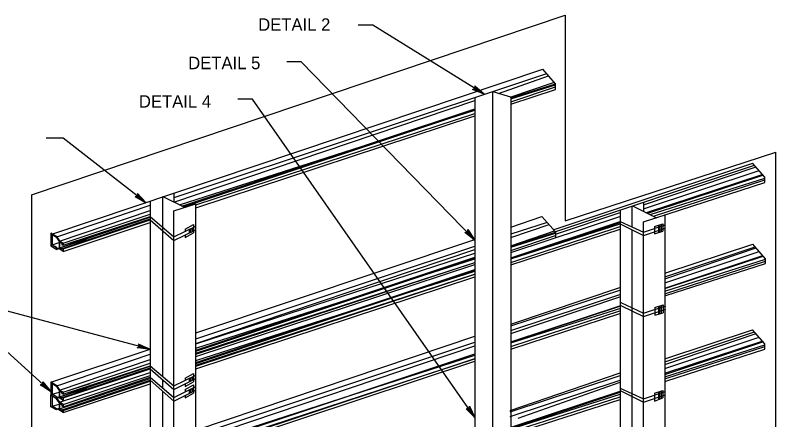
# Model space of a CAD drawing. Extents: x 650495 to 651400, y 297864 to 299646.
# Drawn here: x 650810.5 to 650993.8, y 298185.7 to 298283.1 of the extents above; entities that cross this region are included whole.
import ezdxf

# ---------------------------------------------------------------- set-up
doc = ezdxf.new("R2010")
doc.units = 0
doc.layers.add('2', color=7, linetype='Continuous')
doc.layers.add('3', color=7, linetype='Continuous')

# ---------------------------------------------------------------- blocks, each defined once
blk = doc.blocks.new('RARROW')
at = {"layer": '3'}
blk.add_lwpolyline([(-2.2695, 0.285), (-2.184875, 0.12075), (0, 0), (-2.2695, 0.285), (-2.38575, 0.384625), (0, 0), (-2.183125, -0.108), (-2.262875, -0.2705), (0, 0), (-2.38575, -0.379125), (-2.262875, -0.2705)], dxfattribs=at)

msp = doc.modelspace()

# ---------------------------------------------------------------- linework, layer by layer
at = {"layer": '2'}
for p, q in [((650814.44, 298239.88), (650943.06, 298283.13)), ((650943.06, 298283.13), (650943.06, 298233.63)), ((650896.69, 298280.75), (650893.19, 298280.75)), ((650923.56, 298264.13), (650896.69, 298280.75)), ((650879.44, 298271.88), (650875.94, 298271.88)), ((650921.31, 298229), (650879.44, 298271.88)), ((650819.31, 298230.38), (650937.69, 298270.13)), ((650940.69, 298266.63), (650937.69, 298270.13)), ((650938.56, 298269), (650848.69, 298239.13)), ((650926.97, 298264.31), (650939.06, 298268.5)), ((650929.81, 298263.42), (650940.44, 298267)), ((650929.94, 298263.25), (650940.69, 298266.63)), ((650929.94, 298263), (650940.69, 298266.38)), ((650940.69, 298265.25), (650940.69, 298266.75)), ((650925.56, 298264.68), (650925.56, 298177.88)), ((650929.94, 298263.38), (650925.67, 298264.72)), ((650929.94, 298262.25), (650940.69, 298265.88)), ((650929.94, 298261.75), (650940.69, 298265.25)), ((650848.69, 298238.13), (650921.31, 298262.63)), ((650867.69, 298262.88), (650864.19, 298262.88)), ((650921.31, 298186.25), (650867.69, 298262.88)), ((650921.31, 298263.27), (650921.31, 298176.13)), ((650929.94, 298263.38), (650929.94, 298176.38)), ((650850.69, 298237.13), (650921.31, 298260.63)), ((650850.06, 298237.5), (650921.31, 298260.25)), ((650851.06, 298237), (650921.31, 298260.38)), ((650854.06, 298237.5), (650921.31, 298259.5)), ((650854.06, 298236.75), (650921.31, 298258.88)), ((650822.06, 298253.5), (650817.94, 298253.5)), ((650842.06, 298238), (650822.06, 298253.5)), ((650943.06, 298233.63), (650993.81, 298250.13)), ((650993.81, 298139.38), (650993.81, 298250.13)), ((650940.19, 298231.5), (650988.31, 298247.5)), ((650940.56, 298231), (650988.69, 298247)), ((650961.94, 298237.5), (650989.06, 298246.63)), ((650991.19, 298244.13), (650988.19, 298247.5)), ((650961.94, 298236.5), (650989.81, 298245.75)), ((650962.69, 298235.63), (650990.56, 298244.75)), ((650962.94, 298235.5), (650990.69, 298244.63)), ((650991.19, 298242.88), (650991.19, 298244.13)), ((650961.94, 298233.38), (650991.19, 298242.88)), ((650963.56, 298235.13), (650991.19, 298243.88)), ((650964.31, 298234.75), (650991.19, 298243.5)), ((650814.44, 298240), (650814.44, 298080)), ((650846.06, 298239.5), (650851.31, 298236.88)), ((650846.06, 298196.13), (650846.06, 298239.5)), ((650848.69, 298240.25), (650848.69, 298238.13)), ((650820.56, 298229.75), (650843.06, 298237.38)), ((650843.06, 298238.38), (650843.06, 298070.13)), ((650848.69, 298236), (650854.06, 298237.75)), ((650854.06, 298067.88), (650854.06, 298237.75)), ((650959.19, 298232.13), (650959.19, 298237.25)), ((650959.31, 298237.25), (650965.06, 298234.38)), ((650961.94, 298238), (650961.94, 298236)), ((650821.19, 298228.75), (650843.06, 298236.13)), ((650822.06, 298228.25), (650843.06, 298235.25)), ((650848.69, 298065.25), (650848.69, 298236)), ((650940.69, 298230.38), (650956.31, 298235.63)), ((650956.31, 298236.25), (650956.31, 298110.5)), ((650967.19, 298108.25), (650967.19, 298235.13)), ((650821.19, 298227.13), (650843.06, 298234.5)), ((650821.81, 298227), (650843.06, 298234.13)), ((650822.06, 298227.75), (650843.06, 298234.63)), ((650822.06, 298226.88), (650843.06, 298233.88)), ((650822.06, 298226.25), (650843.06, 298233.25)), ((650843.06, 298234.63), (650848.69, 298229.75)), ((650843.06, 298233.88), (650848.69, 298228.88)), ((650843.06, 298233.25), (650843.06, 298233.25)), ((650929.94, 298226), (650956.44, 298234.75)), ((650929.94, 298232.13), (650937.44, 298234.63)), ((650929.94, 298224.75), (650956.31, 298233.5)), ((650938.69, 298233.25), (650929.94, 298230.38)), ((650929.94, 298224.5), (650956.31, 298233.25)), ((650937.44, 298234.63), (650940.69, 298231)), ((650956.31, 298233.5), (650961.94, 298230.88)), ((650961.94, 298105.63), (650961.94, 298233.38)), ((650848.69, 298229.75), (650854.06, 298232.38)), ((650848.69, 298228.88), (650854.06, 298231.5)), ((650851.44, 298231.63), (650853.44, 298232.75)), ((650851.44, 298231.63), (650851.44, 298231)), ((650852.44, 298231.63), (650852.44, 298230.75)), ((650852.69, 298231.75), (650852.69, 298230.88)), ((650853.06, 298231.88), (650853.06, 298231.13)), ((650853.31, 298232), (650853.31, 298231.25)), ((650853.44, 298232.75), (650853.44, 298230.75)), ((650929.94, 298224.5), (650956.31, 298232.88)), ((650929.94, 298229.63), (650939.19, 298232.75)), ((650929.94, 298223.63), (650956.31, 298232.25)), ((650929.94, 298223), (650956.31, 298231.63)), ((650929.94, 298227.63), (650940.44, 298231.25)), ((650956.31, 298232.88), (650961.94, 298230.13)), ((650959.19, 298108), (650959.19, 298231.5)), ((650961.94, 298230.88), (650967.19, 298232.63)), ((650961.94, 298230.13), (650967.19, 298231.88)), ((650964.56, 298232.25), (650966.56, 298232.88)), ((650964.56, 298232.25), (650964.56, 298230.5)), ((650964.56, 298230.5), (650966.56, 298231.13)), ((650965.56, 298232.63), (650965.56, 298230.75)), ((650965.81, 298232.63), (650965.81, 298230.88)), ((650966.19, 298232.75), (650966.19, 298231)), ((650966.56, 298232.88), (650966.56, 298231.13)), ((650819.06, 298230.63), (650819.06, 298230.63)), ((650820.56, 298229.75), (650819.06, 298230.63)), ((650819.06, 298230.63), (650819.06, 298227.63)), ((650819.06, 298230.63), (650820.56, 298229.75)), ((650819.44, 298230.25), (650819.44, 298227.75)), ((650820.44, 298229.63), (650819.44, 298230.25)), ((650820.44, 298229.63), (650821.06, 298228.63)), ((650820.56, 298229.75), (650821.19, 298228.75)), ((650822.06, 298228.25), (650828.56, 298230.38)), ((650822.06, 298227.75), (650828.56, 298229.88)), ((650851.44, 298229.63), (650853.44, 298230.75)), ((650851.44, 298230.25), (650851.44, 298229.63)), ((650929.94, 298227.5), (650940.69, 298230.88)), ((650929.94, 298227.25), (650940.69, 298230.63)), ((650929.94, 298226.5), (650940.69, 298230.13)), ((650940.69, 298231), (650940.69, 298229.5)), ((650819.06, 298227.63), (650820.56, 298226.75)), ((650819.44, 298227.88), (650821.06, 298228.38)), ((650820.69, 298227), (650819.44, 298227.75)), ((650820.44, 298227.25), (650819.44, 298227.75)), ((650821.06, 298228.75), (650821.06, 298227.13)), ((650821.19, 298227.13), (650827.69, 298229.25)), ((650822.06, 298228.25), (650821.19, 298228.75)), ((650821.81, 298228.13), (650821.19, 298228.5)), ((650821.81, 298228.13), (650821.19, 298228.5)), ((650821.19, 298228.5), (650821.19, 298227.13)), ((650821.81, 298228.13), (650821.81, 298227.88)), ((650821.81, 298227.75), (650821.81, 298228.13)), ((650822.06, 298227.75), (650821.81, 298227.88)), ((650822.06, 298227.75), (650821.81, 298227.75)), ((650822.06, 298228.25), (650822.06, 298227.75)), ((650822.06, 298228.25), (650822.06, 298227.75)), ((650854.06, 298206.63), (650921.31, 298229.13)), ((650854.06, 298205.25), (650921.31, 298227.5)), ((650967.31, 298221.13), (650988.31, 298228)), ((650991.31, 298224.5), (650988.31, 298228)), ((650821.06, 298226.88), (650820.56, 298226.75)), ((650820.69, 298227), (650821.06, 298227.13)), ((650822.06, 298226.25), (650821.06, 298226.88)), ((650821.81, 298226.75), (650821.19, 298227.13)), ((650821.81, 298227), (650821.81, 298226.75)), ((650822.06, 298226.88), (650821.81, 298227)), ((650821.81, 298227), (650821.81, 298226.75)), ((650822.06, 298226.88), (650821.81, 298227)), ((650822.06, 298226.88), (650822.06, 298226.25)), ((650822.06, 298226.88), (650822.06, 298226.25)), ((650854.06, 298204.13), (650921.31, 298226.75)), ((650854.06, 298204), (650921.31, 298225.88)), ((650967.31, 298220.25), (650988.81, 298227.38)), ((650967.31, 298219.75), (650989.06, 298227.13)), ((650967.31, 298218.75), (650989.81, 298226.25)), ((650854.06, 298202.5), (650921.31, 298224.88)), ((650854.06, 298202.25), (650921.31, 298224.63)), ((650854.06, 298203), (650921.31, 298224.5)), ((650967.31, 298217.5), (650990.69, 298225.25)), ((650967.31, 298217.38), (650990.81, 298225.13)), ((650967.31, 298216.75), (650991.31, 298224.38)), ((650967.31, 298216.13), (650991.31, 298223.88)), ((650991.31, 298223.38), (650991.31, 298224.5)), ((650854.06, 298201.5), (650921.31, 298223.63)), ((650854.06, 298201.75), (650921.31, 298223.63)), ((650854.06, 298201), (650921.31, 298223.13)), ((650967.31, 298215.63), (650991.31, 298223.38)), ((650854.06, 298199.5), (650921.31, 298221.88)), ((650854.06, 298199.25), (650921.31, 298221.75)), ((650854.06, 298200), (650921.31, 298221.5)), ((650854.06, 298198.63), (650921.31, 298220.75)), ((650854.06, 298198.88), (650921.19, 298220.75)), ((650854.06, 298198), (650921.31, 298220.13)), ((650929.94, 298208.75), (650956.44, 298217.63)), ((650929.94, 298208.38), (650956.44, 298217)), ((650929.94, 298207.25), (650956.44, 298216)), ((650929.94, 298206.5), (650956.44, 298215.38)), ((650929.94, 298204.5), (650956.44, 298213.25)), ((650929.94, 298204.38), (650956.44, 298213.13)), ((650956.44, 298214), (650961.94, 298211.38)), ((650956.44, 298213.25), (650961.94, 298210.63)), ((650961.94, 298211.38), (650967.31, 298213.13)), ((650964.69, 298212.75), (650966.69, 298213.38)), ((650965.56, 298213), (650965.56, 298211.25)), ((650965.81, 298213.13), (650965.81, 298211.25)), ((650966.19, 298213.25), (650966.19, 298211.38)), ((650966.69, 298213.38), (650966.69, 298211.5)), ((650842.94, 298202.75), (650805.19, 298212.75)), ((650929.94, 298204.25), (650956.44, 298212.63)), ((650929.94, 298203.38), (650956.44, 298212)), ((650929.94, 298202.75), (650956.44, 298211.38)), ((650961.94, 298210.63), (650967.31, 298212.38)), ((650964.69, 298212.75), (650964.69, 298210.88)), ((650964.69, 298210.88), (650966.69, 298211.5)), ((650967.31, 298200.5), (650988.19, 298207.38)), ((650991.19, 298204), (650988.19, 298207.38)), ((650854.06, 298183.25), (650921.31, 298205.88)), ((650967.31, 298199.75), (650988.69, 298206.88)), ((650967.31, 298199.13), (650989.06, 298206.5)), ((650967.31, 298198.13), (650989.81, 298205.63)), ((650819.06, 298192.5), (650806.56, 298203.88)), ((650854.06, 298182), (650921.31, 298204.38)), ((650967.31, 298197), (650990.56, 298204.63)), ((650967.31, 298196.75), (650990.69, 298204.5)), ((650967.31, 298196.13), (650991.19, 298203.75)), ((650991.19, 298202.75), (650991.19, 298204)), ((650819.06, 298194.75), (650843.06, 298202.75)), ((650854.06, 298180.88), (650921.31, 298203.5)), ((650967.31, 298195.63), (650991.19, 298203.38)), ((650967.31, 298195), (650991.19, 298202.75)), ((650820.56, 298193.88), (650843.06, 298201.5)), ((650821.19, 298192.88), (650843.06, 298200.25)), ((650854.06, 298179.25), (650921.31, 298201.63)), ((650854.06, 298179.63), (650921.31, 298201.25)), ((650854.06, 298178.25), (650921.31, 298200.5)), ((650854.06, 298178.5), (650921.19, 298200.38)), ((650821.19, 298191.25), (650843.06, 298198.63)), ((650821.81, 298191.13), (650843.06, 298198.25)), ((650822.06, 298192.38), (650843.06, 298199.38)), ((650822.06, 298191.88), (650843.06, 298198.75)), ((650843.06, 298198.75), (650848.69, 298193.88)), ((650854.06, 298177.63), (650921.31, 298199.88)), ((650821.19, 298190), (650843.06, 298197.13)), ((650822.06, 298191), (650843.06, 298198)), ((650822.06, 298189.38), (650843.06, 298196.38)), ((650843.06, 298198), (650848.69, 298193)), ((650843.06, 298197.38), (650843.06, 298197.38)), ((650848.69, 298193.88), (650854.06, 298196.5)), ((650851.44, 298195.75), (650853.44, 298196.88)), ((650853.44, 298196.88), (650853.44, 298194.88)), ((650929.81, 298188), (650956.31, 298197)), ((650929.81, 298187.63), (650956.31, 298196.38)), ((650820.56, 298193.88), (650819.06, 298194.75)), ((650819.06, 298194.75), (650819.06, 298191.75)), ((650819.06, 298194.75), (650820.56, 298193.88)), ((650821.19, 298188.38), (650843.06, 298195.63)), ((650821.81, 298188.13), (650843.06, 298195.25)), ((650822.06, 298188.88), (650843.06, 298196)), ((650822.06, 298188), (650843.06, 298195)), ((650822.06, 298192.38), (650828.56, 298194.5)), ((650843.06, 298196), (650848.69, 298191.13)), ((650843.06, 298195.25), (650848.69, 298190.25)), ((650843.06, 298194.63), (650843.06, 298194.63)), ((650846.06, 298193.38), (650846.06, 298195.38)), ((650848.69, 298193), (650854.06, 298195.63)), ((650851.44, 298195.75), (650851.44, 298195.25)), ((650851.44, 298193.75), (650853.44, 298194.88)), ((650852.44, 298195.75), (650852.44, 298194.88)), ((650852.69, 298195.88), (650852.69, 298195)), ((650853.06, 298196), (650853.06, 298195.25)), ((650853.31, 298196.13), (650853.31, 298195.38)), ((650929.81, 298186.5), (650956.31, 298195.25)), ((650931.69, 298186.13), (650956.31, 298194.75)), ((650819.44, 298194.38), (650819.44, 298191.88)), ((650820.44, 298193.75), (650819.44, 298194.38)), ((650820.44, 298193.75), (650821.06, 298192.75)), ((650820.56, 298193.88), (650821.19, 298192.88)), ((650821.06, 298192.75), (650821.06, 298191.25)), ((650821.19, 298191.25), (650827.69, 298193.38)), ((650822.06, 298192.38), (650821.19, 298192.88)), ((650821.81, 298192.25), (650821.19, 298192.63)), ((650821.81, 298192.25), (650821.19, 298192.63)), ((650821.19, 298192.63), (650821.19, 298191.25)), ((650822.06, 298187.5), (650843.06, 298194.38)), ((650822.06, 298191.88), (650828.56, 298194)), ((650846.06, 298067.63), (650846.06, 298192.63)), ((650848.69, 298191.13), (650854.06, 298193.75)), ((650848.69, 298190.25), (650854.06, 298192.88)), ((650851.44, 298194.38), (650851.44, 298193.75)), ((650851.44, 298193), (650853.44, 298194.13)), ((650851.44, 298193), (650851.44, 298192.5)), ((650852.44, 298193), (650852.44, 298192.13)), ((650852.69, 298193.13), (650852.69, 298192.25)), ((650853.06, 298193.25), (650853.06, 298192.5)), ((650853.31, 298193.38), (650853.31, 298192.63)), ((650853.44, 298194.13), (650853.44, 298192.13)), ((650929.81, 298183.88), (650956.31, 298192.63)), ((650956.31, 298193.38), (650961.94, 298190.75)), ((650956.31, 298192.75), (650961.94, 298190)), ((650964.56, 298192.13), (650966.56, 298192.75)), ((650966.19, 298192.63), (650966.19, 298190.88)), ((650966.56, 298192.75), (650966.56, 298191)), ((650819.06, 298188.88), (650819.06, 298191.75)), ((650819.06, 298191.75), (650820.56, 298190.88)), ((650819.44, 298191.88), (650821.06, 298192.38)), ((650820.69, 298191.13), (650819.44, 298191.88)), ((650819.44, 298191.38), (650819.44, 298189)), ((650820.44, 298190.75), (650819.44, 298191.38)), ((650821.06, 298191), (650820.56, 298190.88)), ((650820.56, 298190.88), (650821.19, 298190)), ((650820.69, 298191.13), (650821.06, 298191.25)), ((650822.06, 298190.38), (650821.06, 298191)), ((650821.81, 298190.88), (650821.19, 298191.25)), ((650821.81, 298192.25), (650821.81, 298192)), ((650821.81, 298192), (650821.81, 298192.25)), ((650822.06, 298191.88), (650821.81, 298192)), ((650821.81, 298191.13), (650821.81, 298190.88)), ((650822.06, 298191), (650821.81, 298191.13)), ((650821.81, 298191.13), (650821.81, 298190.88)), ((650822.06, 298191), (650821.81, 298191.13)), ((650822.06, 298192.38), (650822.06, 298191.88)), ((650822.06, 298192.38), (650822.06, 298191.88)), ((650822.06, 298191), (650822.06, 298190.38)), ((650822.06, 298191), (650822.06, 298190.38)), ((650851.44, 298191), (650853.44, 298192.13)), ((650851.44, 298191.63), (650851.44, 298191)), ((650929.81, 298183.63), (650956.31, 298192.38)), ((650929.81, 298183.5), (650956.31, 298191.88)), ((650929.81, 298182.75), (650956.31, 298191.25)), ((650961.94, 298190.75), (650967.19, 298192.5)), ((650961.94, 298190), (650967.19, 298191.75)), ((650964.56, 298192.13), (650964.56, 298190.25)), ((650964.56, 298190.25), (650966.56, 298191)), ((650965.56, 298192.38), (650965.56, 298190.63)), ((650965.81, 298192.5), (650965.81, 298190.75)), ((650819.44, 298189), (650821.06, 298189.5)), ((650820.44, 298188.38), (650819.44, 298189)), ((650821.06, 298189.88), (650820.44, 298190.75)), ((650821.06, 298189.88), (650821.06, 298188.5)), ((650822.06, 298189.38), (650821.19, 298190)), ((650821.81, 298189.25), (650821.19, 298189.75)), ((650821.19, 298189.75), (650821.19, 298188.38)), ((650821.81, 298189), (650821.81, 298189.25)), ((650822.06, 298188.88), (650821.81, 298189)), ((650822.06, 298189.38), (650822.06, 298188.88)), ((650929.81, 298182.13), (650956.31, 298190.63)), ((650820.44, 298188.13), (650819.06, 298188.88)), ((650820.44, 298188.38), (650821.06, 298188.5)), ((650820.81, 298188.25), (650820.44, 298188.13)), ((650822.06, 298187.5), (650820.81, 298188.25)), ((650821.81, 298187.88), (650821.19, 298188.38)), ((650821.81, 298188.13), (650821.81, 298187.88)), ((650822.06, 298188), (650821.81, 298188.13)), ((650822.06, 298188), (650822.06, 298187.5))]:
    msp.add_line(p, q, dxfattribs=at)

# ---------------------------------------------------------------- block references
for p, xscale, yscale, rotation in [((650923.56, 298264.13), 1.257434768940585, 1.3092961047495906, -31.505889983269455), ((650842.06, 298238), 1.257434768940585, 1.3092961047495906, -37.30762065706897), ((650921.31, 298229), 1.2574347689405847, 1.3092961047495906, -45.88822886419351), ((650842.94, 298202.75), 1.2574347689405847, 1.3092961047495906, -14.467850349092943), ((650819.06, 298192.5), 1.2574347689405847, 1.3092961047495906, -42.00451374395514), ((650921.31, 298186.25), 1.2574347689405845, 1.3092961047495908, -54.475918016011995)]:
    msp.add_blockref('RARROW', p, dxfattribs=dict(at, xscale=xscale, yscale=yscale, rotation=rotation))

# ---------------------------------------------------------------- texts
for s, p in [('DETAIL 2', (650869.06, 298279.38)), ('DETAIL 5', (650852.19, 298270.13)), ('DETAIL 4', (650840.31, 298260.88))]:
    msp.add_text(s, height=3, dxfattribs=at).set_placement(p)

doc.saveas('drawing.dxf')
